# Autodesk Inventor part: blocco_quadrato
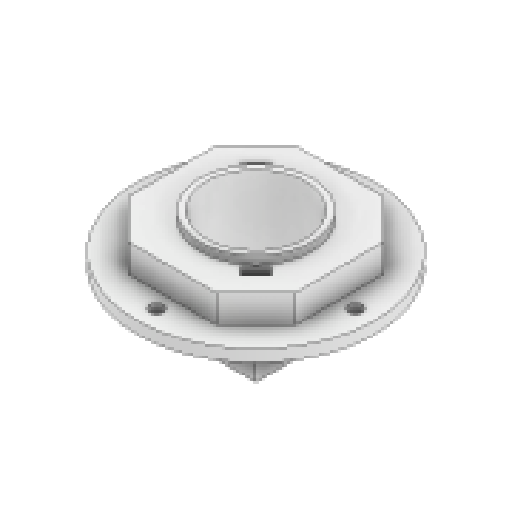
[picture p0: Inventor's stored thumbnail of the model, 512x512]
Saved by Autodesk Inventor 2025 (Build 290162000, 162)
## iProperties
Created: 2025-05
Part Number: blocco_quadrato
Material: Plastica ABS
Document SubType Name: Modeling
Designer: R5800u
Density: 1.06 g/cm^3
Appearance: Liscia - Bianco
Author: R5800u
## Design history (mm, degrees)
sketch "Schizzo1"
  geometry: L1 (17.5, 17.5)-(-17.5, 17.5); L2 (-17.5, 17.5)-(-17.5, -17.5); L3 (-17.5, -17.5)-(17.5, -17.5); L4 (17.5, -17.5)-(17.5, 17.5); L5 (17.5, 17.5)-(-17.5, -17.5); L6 (-17.5, 17.5)-(17.5, -17.5); 1 further point
  constraints: 12 end point, 2 midpoint, 2 parallel, 1 horizontal, 1 perpendicular
  dimensions: "d0" = 35 distance of L3.end L2.end; "d1" = 35 distance of L2.end L1.end
extrude "Estrusione1" new body sketch "Schizzo1" distance "d2" = 8; taper "d3" = 0 deg
sketch "Schizzo2"
  geometry: C1 r 12.5 at (0, 0); 1 further point
  constraints: 1 centre point, 1 coincident
  dimensions: "d4" = 25 diameter of C1
extrude "Estrusione2" cut sketch "Schizzo2" extent not by distance; stored distance "d5" = 0; taper "d6" = 0 deg
sketch "Schizzo6"
  geometry: L1 (-17.5, -17.5)-(17.5, -17.5) reference; L2 (17.5, -17.5)-(17.5, 17.5) reference; L3 (17.5, 17.5)-(-17.5, 17.5) reference; L4 (-17.5, 17.5)-(-17.5, -17.5) reference; L5 (-17.5, -17.5)-(17.5, -17.5) reference; L6 (-21, -21)-(21, -21); L7 (21, -21)-(21, 21); L8 (21, 21)-(-21, 21); L9 (-21, 21)-(-21, -21); L10 (-21, -21)-(21, 21); L11 (21, -21)-(-21, 21); C1 r 12.5 at (0, 0) reference; C2 r 30 at (0, 0); C3 r 12.5 at (0, 0) reference; A1 r 24.749 centre (0, 0) between (17.5, -17.5) and (-17.5, -17.5); 5 further points
  constraints: 12 end point, 2 centre point, 2 coincident, 2 midpoint, 2 parallel, 1 horizontal, 1 perpendicular, 1 point on circle, 1 vertical alignment
  dimensions: "d18" = 60 diameter of C2; "d54" = 42 distance of L8.end L7.end; "d55" = 42 distance of L6.end L7.end
extrude "Estrusione5" join sketch "Schizzo6" distance "d13" = 3; taper "d14" = 0 deg
sketch "Schizzo7"
  geometry: 2 further points
  dimensions: "d20" = 25 distance of point (0, 0) point (25, 0)
hole "Foro1" sketch "Schizzo7" at (25, 0) diameter "d21" = 3.4; stored, may be unused: countersink angle "d25" = 90 deg, drill point angle "d27" = 118 deg; dims "d22" = 10, "d23" = 6.3, "d24" = 2, "d26" = 8
pattern_circular "Serie circolare1" dims angle "d29" = 360 deg
sketch "Schizzo8"
  geometry: L1 (17.5, -17.5)-(17.5, 17.5) reference; L2 (17.5, 17.5)-(-17.5, 17.5) reference; L3 (-17.5, 17.5)-(-17.5, -17.5) reference; L4 (-17.5, -17.5)-(17.5, -17.5) reference; L5 (-21, -21)-(21, -21); L6 (21, -21)-(21, 21); L7 (21, 21)-(-21, 21); L8 (-21, 21)-(-21, -21); L9 (-21, -21)-(21, 21); L10 (21, -21)-(-21, 21); C1 r 12.5 at (0, 0) reference; 1 further point
  constraints: 12 end point, 2 midpoint, 2 parallel, 1 horizontal, 1 perpendicular
  dimensions: "d56" = 42 distance of L7.end L6.end; "d57" = 42 distance of L6.end L5.end
extrude "Estrusione6" join sketch "Schizzo8" distance "d34" = 10; taper "d35" = 0 deg
chamfer "Smusso3" distance "d36" = 10; stored, may be unused: second distance "d37" = 2, angle "d38" = 45 deg
sketch "Schizzo9"
  geometry: L1 (2.8, -17.2)-(-2.8, -17.2); L2 (-2.8, -17.2)-(-2.8, -14.8); L3 (-2.8, -14.8)-(2.8, -14.8); L4 (2.8, -14.8)-(2.8, -17.2); L5 (2.8, -17.2)-(-2.8, -14.8); L6 (-2.8, -17.2)-(2.8, -14.8); L7 (14.142, -10.182)-(10.182, -14.142); L8 (10.182, -14.142)-(8.485, -12.445); L9 (8.485, -12.445)-(12.445, -8.485); L10 (12.445, -8.485)-(14.142, -10.182); L11 (14.142, -10.182)-(8.485, -12.445); L12 (10.182, -14.142)-(12.445, -8.485); L13 (17.2, 2.8)-(17.2, -2.8); L14 (17.2, -2.8)-(14.8, -2.8); L15 (14.8, -2.8)-(14.8, 2.8); L16 (14.8, 2.8)-(17.2, 2.8); L17 (17.2, 2.8)-(14.8, -2.8); L18 (17.2, -2.8)-(14.8, 2.8); L19 (10.182, 14.142)-(14.142, 10.182); L20 (14.142, 10.182)-(12.445, 8.485); L21 (12.445, 8.485)-(8.485, 12.445); L22 (8.485, 12.445)-(10.182, 14.142); L23 (10.182, 14.142)-(12.445, 8.485); L24 (14.142, 10.182)-(8.485, 12.445); L25 (-2.8, 17.2)-(2.8, 17.2); L26 (2.8, 17.2)-(2.8, 14.8); L27 (2.8, 14.8)-(-2.8, 14.8); L28 (-2.8, 14.8)-(-2.8, 17.2); L29 (-2.8, 17.2)-(2.8, 14.8); L30 (2.8, 17.2)-(-2.8, 14.8); L31 (-14.142, 10.182)-(-10.182, 14.142); L32 (-10.182, 14.142)-(-8.485, 12.445); L33 (-8.485, 12.445)-(-12.445, 8.485); L34 (-12.445, 8.485)-(-14.142, 10.182); L35 (-14.142, 10.182)-(-8.485, 12.445); L36 (-10.182, 14.142)-(-12.445, 8.485); L37 (-17.2, -2.8)-(-17.2, 2.8); L38 (-17.2, 2.8)-(-14.8, 2.8); L39 (-14.8, 2.8)-(-14.8, -2.8); L40 (-14.8, -2.8)-(-17.2, -2.8); L41 (-17.2, -2.8)-(-14.8, 2.8); L42 (-17.2, 2.8)-(-14.8, -2.8); L43 (-10.182, -14.142)-(-14.142, -10.182); L44 (-14.142, -10.182)-(-12.445, -8.485); L45 (-12.445, -8.485)-(-8.485, -12.445); L46 (-8.485, -12.445)-(-10.182, -14.142); L47 (-10.182, -14.142)-(-12.445, -8.485); L48 (-14.142, -10.182)-(-8.485, -12.445); C1 r 12.5 at (0, 0) reference; 9 further points
  constraints: 96 end point, 2 midpoint, 2 parallel, 1 horizontal, 1 perpendicular, 89 other
  dimensions: "d39" = 5.6 distance of L2.end L3.end; "d40" = 2.4 distance of L1.end L2.end; "d41" = 16 distance of C1.centre point (0, -16); "d60" = 360 deg dimension on point (0, 0) L1.start (derived)
extrude "Estrusione7" cut sketch "Schizzo9" distance "d42" = 7; taper "d43" = 0 deg
sketch "Schizzo13"
  geometry: L1 (14.142, 7)-(0, 7) reference; L2 (0, 7)-(0, 0) reference; L3 (0, 0)-(14.142, 0) reference; L4 (14.142, 0)-(14.142, 7) reference; L5 (0, 0)-(-15.556, 0) reference; L6 (14.142, 7)-(0, 0); L7 (0, 0)-(0, 7); L8 (0, 0)-(14.142, 0) reference; L9 (0, 7)-(14.142, 0); 2 further points
  constraints: 6 end point, 1 collinear, 1 midpoint
hole "Foro4" sketch "Schizzo13" at (7.071, 3.5) diameter "d69" = 3.4; stored, may be unused: countersink angle "d73" = 90 deg, drill point angle "d75" = 0 deg; dims "d70" = 6, "d71" = 5.5, "d72" = 3, "d74" = 8
sketch "Schizzo14"
  geometry: C1 r 14 at (0, 0); C2 r 12.5 at (0, 0) reference; 1 further point
  constraints: 1 centre point, 1 coincident
  dimensions: "d76" = 28 diameter of C1
extrude "Estrusione9" join sketch "Schizzo14" distance "d77" = 2; taper "d78" = 0 deg
sketch "Schizzo17"
  geometry: L1 (10.304, 3.5)-(8.688, 0.7); L2 (8.688, 0.7)-(5.454, 0.7); L3 (5.454, 0.7)-(3.838, 3.5); L4 (3.838, 3.5)-(5.454, 6.3); L5 (5.454, 6.3)-(8.688, 6.3); L6 (8.688, 6.3)-(10.304, 3.5); C1 r 1.7 at (7.071, 3.5) reference; 2 further points
  constraints: 12 end point, 1 coincident, 13 other
  dimensions: "d79" = 5.6 distance between parallel lines of L5 L2
extrude "Estrusione10" cut sketch "Schizzo17" distance "d80" = 3; taper "d81" = 0 deg
node "Solido1"
node "Linea chiusa proiettata2"
node "Linea chiusa proiettata3"
node "Schizzo - Serie circolare1" dims "d60" = 360 deg (derived)
node "Linea chiusa proiettata5"
